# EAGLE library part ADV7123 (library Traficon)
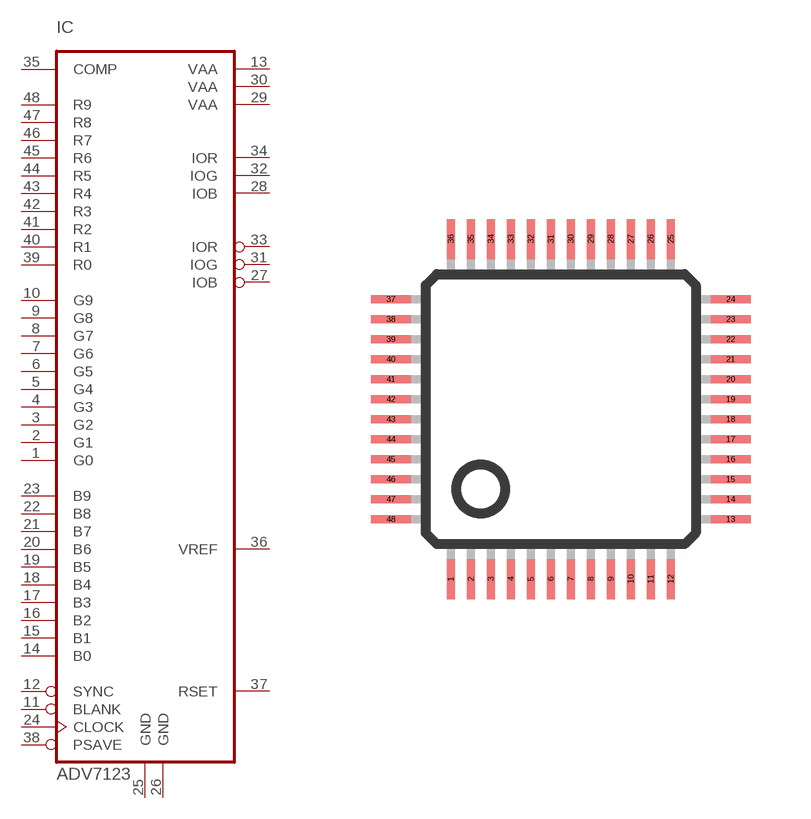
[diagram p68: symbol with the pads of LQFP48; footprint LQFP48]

Designator prefix IC

## ADV7123  [LQFP48]
1  G0
2  G1
3  G2
4  G3
5  G4
6  G5
7  G6
8  G7
9  G8
10  G9
11  BLANK
12  SYNC
13  VAA
14  B0
15  B1
16  B2
17  B3
18  B4
19  B5
20  B6
21  B7
22  B8
23  B9
24  CLOCK
25  GND
26  GND
27  IOB
28  IOB
29  VAA
30  VAA
31  IOG
32  IOG
33  IOR
34  IOR
35  COMP
36  VREF
37  RSET
38  PSAVE
39  R0
40  R1
41  R2
42  R3
43  R4
44  R5
45  R6
46  R7
47  R8
48  R9

## Footprint LQFP48 (pad centres in mm)
48-pin plastic LQFP (FPT-48P-M26) www.fma.fujitsu.com/pdf/e713717.pdf
smd 0.2 x 1: 1 -2.75,-4.25; 2 -2.25,-4.25; 3 -1.75,-4.25; 4 -1.25,-4.25; 5 -0.75,-4.25; 6 -0.25,-4.25; 7 0.25,-4.25; 8 0.75,-4.25; 9 1.25,-4.25; 10 1.75,-4.25; 11 2.25,-4.25; 12 2.75,-4.25; 25 2.75,4.25; 26 2.25,4.25; 27 1.75,4.25; 28 1.25,4.25; 29 0.75,4.25; 30 0.25,4.25; 31 -0.25,4.25; 32 -0.75,4.25; 33 -1.25,4.25; 34 -1.75,4.25; 35 -2.25,4.25; 36 -2.75,4.25
smd 1 x 0.2: 13 4.25,-2.75; 14 4.25,-2.25; 15 4.25,-1.75; 16 4.25,-1.25; 17 4.25,-0.75; 18 4.25,-0.25; 19 4.25,0.25; 20 4.25,0.75; 21 4.25,1.25; 22 4.25,1.75; 23 4.25,2.25; 24 4.25,2.75; 37 -4.25,2.75; 38 -4.25,2.25; 39 -4.25,1.75; 40 -4.25,1.25; 41 -4.25,0.75; 42 -4.25,0.25; 43 -4.25,-0.25; 44 -4.25,-0.75; 45 -4.25,-1.25; 46 -4.25,-1.75; 47 -4.25,-2.25; 48 -4.25,-2.75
